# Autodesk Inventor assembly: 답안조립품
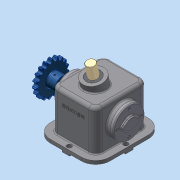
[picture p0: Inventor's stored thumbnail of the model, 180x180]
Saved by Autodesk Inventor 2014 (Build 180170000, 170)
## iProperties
Created: 2014-11
Part Number: 답안조립품
Document SubType Name: Assembly
Designer: user
Author: user
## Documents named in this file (13)
- C:\Users\user\Desktop\441122V1016\답안조립품.iam
- C:\Users\user\Desktop\441122V1016\본체.ipt
- C:\Users\user\Desktop\441122V1016\뒤커버.ipt
- C:\Users\user\Desktop\441122V1016\앞커버.ipt
- C:\Users\user\Desktop\441122V1016\베어링 6205.ipt
- C:\Users\user\Desktop\441122V1016\편심축.ipt
- C:\Users\user\Desktop\441122V1016\슬라이드.ipt
- C:\Users\user\Desktop\441122V1016\부시.ipt
- C:\Users\user\Desktop\441122V1016\오일실.ipt
- C:\Users\user\Desktop\441122V1016\키 8x8.ipt
- C:\Users\user\Desktop\441122V1016\5-체인 스프로킷.ipt
- C:\Users\user\Desktop\441122V1016\멈춤나사 M5x0.5.ipt
- C:\Users\user\Desktop\441122V1016\M4x0.5.ipt
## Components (9 placed, 2 different names)
1. 5-체인 스프로킷:1
2. M4x0.5:1 — 각도:5
3. M4x0.5:2 — 각도:8
4. M4x0.5:3 — 각도:7
5. M4x0.5:4 — 각도:4
6. M4x0.5:5 — 각도:2
7. M4x0.5:6 — 각도:1
8. M4x0.5:7 — 각도:3
9. M4x0.5:8 — 각도:6
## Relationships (8: Angle 8)
- 각도:1 [Angle]: M4x0.5:6
- 각도:2 [Angle]: M4x0.5:5
- 각도:3 [Angle]: M4x0.5:7
- 각도:4 [Angle]: M4x0.5:4
- 각도:5 [Angle]: M4x0.5:1
- 각도:6 [Angle]: M4x0.5:8
- 각도:7 [Angle]: M4x0.5:3
- 각도:8 [Angle]: M4x0.5:2
